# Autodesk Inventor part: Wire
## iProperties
Shininess: 64.0
Length Units: 11269
Angle Units: 11279
Time Units: 11290
Mass Units: 11283
Length Display Precision: 3
Angle Display Precision: 2
Compacted: True
Part Number: Wire
Document SubType Name: Modeling
Created: 2003-02
Material: Standard
Designer: hofer_a
Density: 0.0
Volumn: 0.0
Area: 0.0
PropertySet Name: Model Information
Control State: 0
Master: False
Checked Out: False
Author: hofer_a
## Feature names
1. Extrusion1
2. Extrusion2
3. Rundung1 [Fillet]
4. Rundung2 [Fillet]
5. Rundung3 [Fillet]
6. Extrusion3
